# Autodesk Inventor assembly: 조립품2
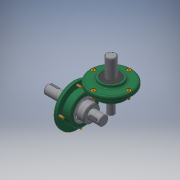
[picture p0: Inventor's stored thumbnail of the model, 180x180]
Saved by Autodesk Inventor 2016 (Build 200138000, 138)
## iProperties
Created: 2016-09
Part Number: 조립품2
Document SubType Name: Assembly
Designer: Administrator
Author: Administrator
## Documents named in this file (12)
- D:\460907V1005\조립품2.iam
- D:\460907V1005\부품1.ipt
- D:\460907V1005\커버.ipt
- D:\460907V1005\M4.ipt
- D:\460907V1005\오일실 17 32 8.ipt
- D:\460907V1005\베어링 6203.ipt
- D:\460907V1005\메인 축.ipt
- 메인 축.ipt
- D:\460907V1005\키 5x5.ipt
- D:\460907V1005\서브 축.ipt
- 서브 축.ipt
- D:\460907V1005\키 4x4.ipt
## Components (8 placed, 1 different names)
1. M4:1
2. M4:2
3. M4:3
4. M4:4
5. M4:5
6. M4:6
7. M4:7
8. M4:8
